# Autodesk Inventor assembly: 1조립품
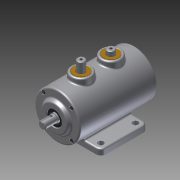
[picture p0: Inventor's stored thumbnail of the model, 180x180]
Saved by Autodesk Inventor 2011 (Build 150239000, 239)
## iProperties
Created: 2015-04
Part Number: 1조립품
Document SubType Name: Assembly
Designer: user
Author: user
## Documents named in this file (10)
- D:\441225V1007\1조립품.iam
- D:\441225V1007\1.본체.ipt
- D:\441225V1007\2.축.ipt
- D:\441225V1007\M4-소켓머리.ipt
- D:\441225V1007\뒷커버.ipt
- D:\441225V1007\베어링 6203.ipt
- D:\441225V1007\부시.ipt
- D:\441225V1007\슬라이더.ipt
- D:\441225V1007\앞커버.ipt
- D:\441225V1007\오일실.ipt
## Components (13 placed, 5 different names)
1. 1.본체:1
2. 2.축:1
3. 9-M4-소켓머리:1
4. 7-베어링 6203:1
5. 8-오일실:1
6. 9-M4-소켓머리:2
7. 9-M4-소켓머리:3
8. 9-M4-소켓머리:4
9. 9-M4-소켓머리:5
10. 9-M4-소켓머리:6
11. 9-M4-소켓머리:7
12. 9-M4-소켓머리:8
13. 7-베어링 6203:2
